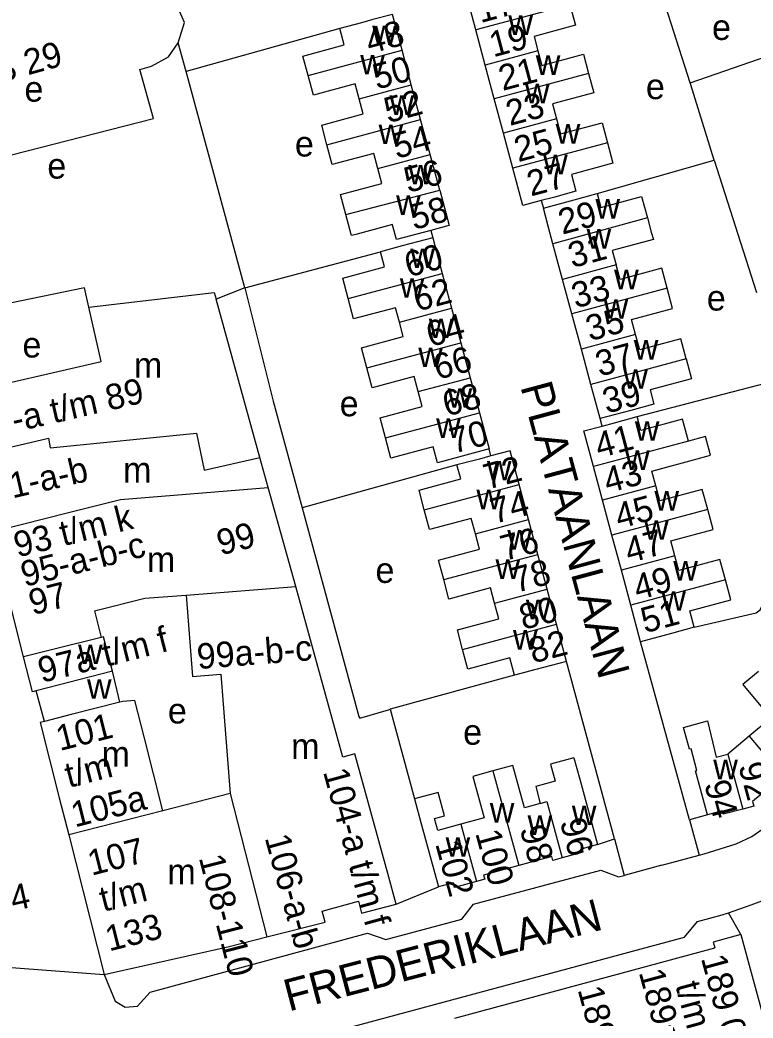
# Model space of a CAD drawing. Extents: x 159261 to 160849, y 382514 to 384534.
# Drawn here: x 159763.1 to 159878.4, y 383626.8 to 383783.7 of the extents above; entities that cross this region are included whole.
import ezdxf

# ---------------------------------------------------------------- set-up
doc = ezdxf.new("R2010")
doc.units = 0
for name, color, linetype in [('BLT_Basislijn', 7, 'Continuous'), ('BLT_Bebouwing', 7, 'Continuous'), ('BLT_Centroide', 7, 'Continuous'), ('BLT_Huisnummer', 7, 'Continuous'), ('BLT_Huisnummer_ tussenligend', 7, 'Continuous'), ('BLT_Huisnummer_reeks', 7, 'Continuous'), ('BLT_Onderdoorgang_en_onderverdeling', 7, 'Continuous'), ('BLT_Onderverdeling_panden', 7, 'Continuous'), ('BLT_Straatnaam', 7, 'Continuous'), ('BLT_Vlakafsluiter', 7, 'Continuous')]:
    doc.layers.add(name, color=color, linetype=linetype)

msp = doc.modelspace()

# ---------------------------------------------------------------- linework, layer by layer
at = {"layer": 'BLT_Basislijn'}
for p, q in [((159868.5, 383773.83), (159861.68, 383795.07)), ((159813.41, 383782.38), (159789.22, 383775.61)), ((159868.5, 383773.83), (159889.59, 383781.16)), ((159789.22, 383775.61), (159787.98, 383780.15)), ((159798.48, 383741.59), (159789.22, 383775.61)), ((159853.84, 383756.43), (159872.27, 383761.67)), ((159872.27, 383761.67), (159878.89, 383740.89)), ((159845.07, 383755.33), (159845.4, 383754.16)), ((159827.7, 383750.65), (159828.01, 383749.49)), ((159798.48, 383741.59), (159819.77, 383747.29)), ((159773.27, 383741.61), (159761.57, 383739.18)), ((159773.95, 383738.57), (159773.27, 383741.61)), ((159798.48, 383741.59), (159793.96, 383739.82)), ((159860.15, 383721.37), (159882.97, 383727.32)), ((159854.65, 383719.89), (159854.34, 383721.05)), ((159837.15, 383715.19), (159836.87, 383716.29)), ((159831.81, 383713.76), (159807.47, 383707.02)), ((159840.88, 383680.71), (159821.3, 383675.35)), ((159821.3, 383675.35), (159825.15, 383661.25)), ((159868.35, 383657.96), (159869.88, 383652.4)), ((159853.9, 383654.08), (159856.58, 383654.98)), ((159856.58, 383654.98), (159858.12, 383649.24)), ((159864, 383650.82), (159869.88, 383652.4)), ((159822.26, 383644.7), (159828.93, 383647.41)), ((159874.52, 383643.34), (159878.06, 383644.62)), ((159876.46, 383639.92), (159874.52, 383643.34))]:
    msp.add_line(p, q, dxfattribs=at)
for points in [[(159787.98, 383780.15), (159788.98, 383783.33), (159783.92, 383794.95)], [(159752.73, 383760.22), (159784.09, 383768.23), (159781.95, 383775.97), (159783.82, 383776.48), (159786.45, 383777.94), (159787.98, 383780.15)], [(159872.27, 383761.67), (159868.6, 383773.51), (159868.5, 383773.83)], [(159798.48, 383741.59), (159802.9, 383723.8), (159807.47, 383707.02)], [(159869.12, 383688.25), (159878.88, 383690.49), (159879.48, 383690.98), (159888.39, 383709.56), (159886.32, 383716.89), (159886.07, 383717.69)], [(159807.47, 383707.02), (159816.41, 383674.2), (159816.57, 383673.98), (159821.04, 383675.27), (159821.3, 383675.35)], [(159869.88, 383652.4), (159870.7, 383652.62), (159875.73, 383654.2), (159878.19, 383655.34), (159880.26, 383656.82), (159930.33, 383698.35)], [(159868.35, 383657.96), (159860.69, 383685.98)], [(159856.58, 383654.98), (159849.05, 383682.87)], [(159871.18, 383658.76), (159868.35, 383657.96)], [(159776.35, 383633.63), (159778.09, 383629.44), (159779.67, 383628.54), (159781.61, 383628.67), (159783.56, 383630.88), (159817.73, 383640.16), (159820.61, 383639.14), (159832.6, 383642.37), (159834.44, 383644.69), (159854.41, 383650.08), (159857.2, 383648.99), (159858.12, 383649.24)], [(159725.13, 383596.31), (159739.83, 383603.42), (159742.55, 383603.23), (159749.01, 383606.26), (159762.28, 383611.2), (159764.12, 383613.36), (159766.32, 383614.18), (159784.07, 383618.95), (159787.06, 383617.81), (159867.59, 383639.52), (159869.65, 383641.98), (159873.49, 383643.02), (159874.52, 383643.34)]]:
    msp.add_lwpolyline(points, dxfattribs=at)
at = {"layer": 'BLT_Bebouwing'}
for p, q in [((159834.78, 383782.16), (159833.28, 383787.73)), ((159836.25, 383776.65), (159834.78, 383782.16)), ((159824.64, 383773.54), (159823.18, 383778.96)), ((159837.68, 383771.32), (159836.25, 383776.65)), ((159826.11, 383768.07), (159824.64, 383773.54)), ((159839.12, 383765.94), (159837.68, 383771.32)), ((159827.59, 383762.59), (159826.11, 383768.07)), ((159840.6, 383760.41), (159839.12, 383765.94)), ((159829.1, 383756.99), (159827.59, 383762.59)), ((159828.01, 383749.49), (159829.5, 383743.89)), ((159848.42, 383742.94), (159846.91, 383748.55)), ((159829.5, 383743.89), (159830.97, 383738.4)), ((159849.89, 383737.51), (159848.42, 383742.94)), ((159800.85, 383714.93), (159793.96, 383739.82)), ((159775.88, 383730.03), (159773.95, 383738.57)), ((159830.97, 383738.4), (159832.41, 383732.98)), ((159851.39, 383731.96), (159849.89, 383737.51)), ((159832.41, 383732.98), (159833.88, 383727.48)), ((159852.88, 383726.43), (159851.39, 383731.96)), ((159833.88, 383727.48), (159835.35, 383721.96)), ((159854.34, 383721.05), (159852.88, 383726.43)), ((159835.35, 383721.96), (159836.87, 383716.29)), ((159802.16, 383710.2), (159800.85, 383714.93)), ((159854.7, 383708.21), (159853.27, 383713.51)), ((159806.46, 383694.65), (159802.16, 383710.2)), ((159843.07, 383705.18), (159841.59, 383710.7)), ((159856.18, 383702.71), (159854.7, 383708.21)), ((159844.54, 383699.7), (159843.07, 383705.18)), ((159857.66, 383697.22), (159856.18, 383702.71)), ((159846.01, 383694.23), (159844.54, 383699.7)), ((159859.14, 383691.72), (159857.66, 383697.22)), ((159809.94, 383682.06), (159806.46, 383694.65)), ((159847.48, 383688.72), (159846.01, 383694.23)), ((159774.84, 383690.84), (159782.76, 383692.81)), ((159782.76, 383692.81), (159789.23, 383693.28)), ((159860.69, 383685.98), (159859.14, 383691.72)), ((159774.84, 383690.84), (159775.89, 383686.64)), ((159778.84, 383676.45), (159777.64, 383681.32)), ((159794.69, 383680.85), (159796.17, 383662.09)), ((159766.96, 383673.44), (159765.65, 383678.24)), ((159766.96, 383673.44), (159766.3, 383673.28)), ((159766.3, 383673.28), (159767.83, 383667.26)), ((159784.1, 383665.19), (159782.62, 383671)), ((159877.77, 383671.12), (159874.38, 383668.31)), ((159767.83, 383667.26), (159769.3, 383661.44)), ((159785.57, 383659.37), (159784.1, 383665.19)), ((159769.3, 383661.44), (159770.78, 383655.62)), ((159770.78, 383655.62), (159776.35, 383633.63)), ((159831.46, 383626.81), (159872.35, 383637.87))]:
    msp.add_line(p, q, dxfattribs=at)
for points in [[(159849.57, 383786.12), (159850.43, 383782.89), (159843.94, 383781.15), (159844.55, 383778.87)], [(159818.6, 383783.78), (159816.83, 383783.3), (159813.41, 383782.38)], [(159823.18, 383778.96), (159821.66, 383784.6), (159818.6, 383783.78)], [(159808.44, 383774.99), (159807.61, 383778.06), (159814.1, 383779.81), (159813.41, 383782.38)], [(159844.55, 383778.87), (159845.16, 383776.59), (159851.69, 383778.33), (159852.5, 383775.3)], [(159816.46, 383771.33), (159815.82, 383773.68), (159809.27, 383771.92), (159808.44, 383774.99)], [(159852.5, 383775.3), (159853.32, 383772.26), (159846.83, 383770.52), (159847.46, 383768.17)], [(159811.38, 383764.1), (159810.55, 383767.21), (159817.09, 383768.97), (159816.46, 383771.33)], [(159847.46, 383768.17), (159848.08, 383765.82), (159854.64, 383767.58), (159855.49, 383764.39)], [(159819.39, 383760.38), (159818.75, 383762.75), (159812.22, 383760.99), (159811.38, 383764.1)], [(159855.49, 383764.39), (159856.34, 383761.21), (159849.81, 383759.46), (159850.53, 383756.79), (159847, 383755.84), (159845.07, 383755.33)], [(159814.35, 383753.13), (159813.53, 383756.27), (159820.02, 383758.02), (159819.39, 383760.38)], [(159845.07, 383755.33), (159842.17, 383754.55), (159840.6, 383760.41)], [(159829.1, 383756.99), (159830.59, 383751.43), (159830.18, 383751.32), (159827.7, 383750.65)], [(159845.4, 383754.16), (159850.23, 383755.46), (159853.84, 383756.43)], [(159853.84, 383756.43), (159854.43, 383754.24), (159860.83, 383755.98), (159861.76, 383752.6)], [(159846.91, 383748.55), (159846.16, 383751.32), (159845.4, 383754.16)], [(159827.7, 383750.65), (159822.32, 383749.19), (159821.74, 383751.32), (159821.67, 383751.55), (159815.9, 383750), (159815.22, 383749.82), (159815.17, 383750), (159814.35, 383753.13)], [(159861.76, 383752.6), (159862.37, 383750.37), (159862.72, 383749.24), (159856.23, 383747.49), (159856.85, 383745.21)], [(159828.01, 383749.49), (159823.18, 383748.2), (159819.77, 383747.29)], [(159814.7, 383739.94), (159813.85, 383743.16), (159820.41, 383744.91), (159819.77, 383747.29)], [(159864.86, 383741.54), (159864.01, 383744.71), (159857.46, 383742.94), (159856.85, 383745.21)], [(159859.9, 383734.26), (159859.26, 383736.64), (159865.71, 383738.38), (159864.86, 383741.54)], [(159773.95, 383738.57), (159793.67, 383740.87), (159793.96, 383739.82)], [(159822.78, 383736.21), (159822.17, 383738.49), (159815.56, 383736.72), (159814.7, 383739.94)], [(159817.64, 383729.03), (159816.8, 383732.18), (159823.38, 383733.94), (159822.78, 383736.21)], [(159867.84, 383730.47), (159866.99, 383733.61), (159860.55, 383731.87), (159859.9, 383734.26)], [(159867.84, 383730.47), (159868.69, 383727.33), (159862.19, 383725.57), (159862.76, 383723.32), (159859.16, 383722.35), (159854.34, 383721.05)], [(159753.55, 383724.92), (159775.88, 383730.03)], [(159825.71, 383725.3), (159825.09, 383727.65), (159818.48, 383725.88), (159817.64, 383729.03)], [(159820.6, 383718.02), (159819.75, 383721.2), (159826.34, 383722.96), (159825.71, 383725.3)], [(159854.65, 383719.89), (159856.59, 383720.41), (159860.15, 383721.37)], [(159868.21, 383717.53), (159867.29, 383720.94), (159860.74, 383719.17), (159860.15, 383721.37)], [(159853.27, 383713.51), (159851.76, 383719.11), (159854.65, 383719.89)], [(159836.87, 383716.29), (159832.04, 383715), (159828.75, 383714.12), (159828.08, 383716.62), (159821.44, 383714.85), (159820.6, 383718.02)], [(159863.1, 383710.47), (159862.47, 383712.81), (159869, 383714.57), (159871.68, 383715.29), (159870.88, 383718.25), (159868.21, 383717.53)], [(159837.15, 383715.19), (159835.35, 383714.7), (159831.81, 383713.76)], [(159841.59, 383710.7), (159840.18, 383716), (159837.15, 383715.19)], [(159826.68, 383706.7), (159825.85, 383709.8), (159832.4, 383711.56), (159831.81, 383713.76)], [(159871.23, 383706.77), (159870.38, 383709.92), (159863.73, 383708.13), (159863.1, 383710.47)], [(159866.08, 383699.49), (159865.45, 383701.82), (159872.08, 383703.61), (159871.23, 383706.77)], [(159834.71, 383702.94), (159834.07, 383705.36), (159827.51, 383703.6), (159826.68, 383706.7)], [(159763.65, 383683.59), (159759.43, 383700.31), (159761.45, 383700.79), (159760.99, 383702.63), (159759.42, 383703.42)], [(159829.73, 383695.74), (159828.91, 383698.79), (159835.36, 383700.51), (159834.71, 383702.94)], [(159874.01, 383695.73), (159873.16, 383698.89), (159866.71, 383697.15), (159866.08, 383699.49)], [(159837.73, 383692.01), (159837.08, 383694.44), (159830.55, 383692.69), (159829.73, 383695.74)], [(159869.12, 383688.25), (159868.42, 383690.83), (159874.87, 383692.57), (159874.01, 383695.73)], [(159789.23, 383693.28), (159790.24, 383680.5), (159794.69, 383680.85)], [(159832.7, 383684.76), (159831.88, 383687.85), (159838.38, 383689.59), (159837.73, 383692.01)], [(159849.05, 383682.87), (159847.48, 383688.72)], [(159869.12, 383688.25), (159865.52, 383687.28), (159860.69, 383685.98)], [(159775.89, 383686.64), (159768.5, 383684.8), (159763.65, 383683.59)], [(159777.64, 383681.32), (159776.25, 383686.73), (159775.89, 383686.64)], [(159765.65, 383678.24), (159765.07, 383678.09), (159763.65, 383683.59)], [(159840.88, 383680.71), (159840.15, 383683.44), (159833.53, 383681.67), (159832.7, 383684.76)], [(159822.26, 383644.7), (159820.93, 383649.52), (159815.75, 383668.35), (159813.88, 383667.83), (159809.94, 383682.06)], [(159849.05, 383682.87), (159844.21, 383681.59), (159840.88, 383680.71)], [(159879.24, 383681.31), (159876.75, 383679.24), (159881.15, 383673.94), (159877.77, 383671.12)], [(159778.84, 383676.45), (159771.15, 383674.51), (159766.96, 383673.44)], [(159782.62, 383671), (159781.17, 383676.74), (159779.31, 383676.57), (159778.84, 383676.45)], [(159867.45, 383672.51), (159871.21, 383673.53), (159872.54, 383667.8), (159874.38, 383668.31)], [(159871.18, 383658.76), (159869.31, 383665.67), (159869.53, 383665.73), (159868.61, 383669.13), (159868.38, 383669.07), (159867.45, 383672.51)], [(159850.2, 383667.73), (159846.53, 383666.73), (159847.26, 383664.04), (159844.19, 383663.2), (159844.91, 383660.54)], [(159850.2, 383667.73), (159851.12, 383664.34), (159853.9, 383654.08)], [(159844.91, 383660.54), (159842.43, 383659.86), (159840.61, 383666.52), (159837.46, 383665.66)], [(159837.46, 383665.66), (159834.32, 383664.8), (159836.11, 383658.27), (159832.45, 383657.27)], [(159883.04, 383664.77), (159878.3, 383660.84), (159878.49, 383660.14), (159876.76, 383659.67)], [(159796.17, 383662.09), (159785.57, 383659.37)], [(159832.45, 383657.27), (159828.79, 383656.27), (159828.27, 383658.17), (159829.87, 383658.6), (159828.87, 383662.27), (159825.15, 383661.25)], [(159825.15, 383661.25), (159826.15, 383657.57), (159827.61, 383652.23), (159828.93, 383647.41)], [(159876.76, 383659.67), (159873.68, 383658.84), (159873.53, 383659.4), (159871.18, 383658.76)], [(159853.9, 383654.08), (159851.48, 383653.42), (159851.63, 383652.86), (159848.38, 383651.97)], [(159848.38, 383651.97), (159846.89, 383651.56), (159846.71, 383652.21), (159841.53, 383650.79)], [(159841.53, 383650.79), (159836.01, 383649.29), (159836.19, 383648.62), (159834.91, 383648.27)], [(159834.91, 383648.27), (159831.44, 383647.32), (159831.25, 383648.04), (159828.93, 383647.41)], [(159801.95, 383639.55), (159811.11, 383641.87), (159810.64, 383643.6), (159816.36, 383645.18), (159816.83, 383643.32), (159822.26, 383644.7)], [(159776.35, 383633.63), (159796.01, 383638.05), (159801.95, 383639.55)], [(159876.46, 383639.92), (159872.11, 383638.75), (159872.35, 383637.87)], [(159876.46, 383639.92), (159880.62, 383624.55), (159878.71, 383624.02), (159879.98, 383619.32)]]:
    msp.add_lwpolyline(points, dxfattribs=at)
at = {"layer": 'BLT_Onderdoorgang_en_onderverdeling'}
msp.add_line((159777.64, 383681.32), (159765.65, 383678.24), dxfattribs=at)
at = {"layer": 'BLT_Onderverdeling_panden'}
for p, q in [((159849.57, 383786.12), (159834.78, 383782.16)), ((159808.44, 383774.99), (159823.18, 383778.96)), ((159844.55, 383778.87), (159836.25, 383776.65)), ((159852.5, 383775.3), (159837.68, 383771.32)), ((159816.46, 383771.33), (159824.64, 383773.54)), ((159811.38, 383764.1), (159826.11, 383768.07)), ((159847.46, 383768.17), (159839.12, 383765.94)), ((159855.49, 383764.39), (159840.6, 383760.41)), ((159819.39, 383760.38), (159827.59, 383762.59)), ((159814.35, 383753.13), (159829.1, 383756.99)), ((159861.76, 383752.6), (159846.91, 383748.55)), ((159856.85, 383745.21), (159848.42, 383742.94)), ((159814.7, 383739.94), (159829.5, 383743.89)), ((159864.86, 383741.54), (159849.89, 383737.51)), ((159822.78, 383736.21), (159830.97, 383738.4)), ((159859.9, 383734.26), (159851.39, 383731.96)), ((159817.64, 383729.03), (159832.41, 383732.98)), ((159867.84, 383730.47), (159852.88, 383726.43)), ((159825.71, 383725.3), (159833.88, 383727.48)), ((159820.6, 383718.02), (159835.35, 383721.96)), ((159767.88, 383716.44), (159790.86, 383718.78)), ((159868.21, 383717.53), (159853.27, 383713.51)), ((159778.9, 383708.36), (159802.16, 383710.2)), ((159826.68, 383706.7), (159841.59, 383710.7)), ((159863.1, 383710.47), (159854.7, 383708.21)), ((159770.98, 383706.35), (159778.9, 383708.36)), ((159871.23, 383706.77), (159856.18, 383702.71)), ((159759.42, 383703.42), (159770.98, 383706.35)), ((159834.71, 383702.94), (159843.07, 383705.18)), ((159829.73, 383695.74), (159844.54, 383699.7)), ((159866.08, 383699.49), (159857.66, 383697.22)), ((159789.23, 383693.28), (159806.46, 383694.65)), ((159837.73, 383692.01), (159846.01, 383694.23)), ((159874.01, 383695.73), (159859.14, 383691.72)), ((159832.7, 383684.76), (159847.48, 383688.72)), ((159877.77, 383671.12), (159883.04, 383664.77)), ((159874.38, 383668.31), (159876.76, 383659.67)), ((159837.46, 383665.66), (159841.53, 383650.79)), ((159796.17, 383662.09), (159801.95, 383639.55)), ((159785.57, 383659.37), (159770.78, 383655.62)), ((159832.45, 383657.27), (159834.91, 383648.27))]:
    msp.add_line(p, q, dxfattribs=at)
for points in [[(159755.76, 383715.2), (159767.58, 383717.96), (159767.88, 383716.44)], [(159790.86, 383718.78), (159792.07, 383712.94), (159800.85, 383714.93)], [(159844.91, 383660.54), (159845.96, 383660.83), (159848.38, 383651.97)]]:
    msp.add_lwpolyline(points, dxfattribs=at)
at = {"layer": 'BLT_Vlakafsluiter'}
for p, q in [((159864, 383650.82), (159858.12, 383649.24)), ((159878.06, 383644.62), (159881.6, 383645.9)), ((159761.06, 383634.82), (159776.35, 383633.63))]:
    msp.add_line(p, q, dxfattribs=at)

# ---------------------------------------------------------------- texts
at = {"layer": 'BLT_Centroide'}
for s, p in [('w', (159839.9, 383781.38)), ('e', (159871.92, 383780.59)), ('w', (159818.49, 383779.78)), ('w', (159816.61, 383775.16)), ('w', (159844.21, 383775.09)), ('e', (159861.52, 383771.28)), ('e', (159763.82, 383770.89)), ('w', (159842.52, 383770.62)), ('w', (159821.21, 383768.81)), ('w', (159819.49, 383764.22)), ('w', (159847.34, 383764.28)), ('e', (159806.34, 383762.26)), ('e', (159767.42, 383758.79)), ('w', (159845.36, 383759.47)), ('w', (159824.16, 383757.88)), ('w', (159822.25, 383753.09)), ('w', (159853.59, 383752.5)), ('w', (159852.2, 383747.78)), ('w', (159824.48, 383744.72)), ('w', (159856.52, 383741.38)), ('w', (159822.83, 383740.06)), ('w', (159854.88, 383736.75)), ('e', (159871.1, 383738.04)), ('w', (159827.38, 383733.72)), ('e', (159763.51, 383730.66)), ('w', (159825.74, 383729.16)), ('w', (159859.61, 383730.34)), ('m', (159781.03, 383727.47)), ('w', (159857.97, 383725.75)), ('w', (159830.35, 383722.75)), ('e', (159813.38, 383721.42)), ('w', (159828.54, 383718.03)), ('w', (159859.78, 383717.56)), ('w', (159858.25, 383712.97)), ('m', (159779.33, 383711)), ('w', (159836.52, 383711.34)), ('w', (159834.88, 383706.81)), ('w', (159862.86, 383706.59)), ('w', (159861.23, 383702)), ('w', (159839.74, 383700.47)), ('m', (159783.07, 383696.91)), ('w', (159837.88, 383695.84)), ('e', (159819.01, 383695.22)), ('w', (159865.82, 383695.59)), ('w', (159863.94, 383690.84)), ('w', (159842.65, 383689.5)), ('w', (159840.63, 383684.72)), ('w', (159772.25, 383682.45)), ('w', (159773.66, 383677)), ('e', (159786.37, 383673.12)), ('e', (159832.79, 383669.78)), ('m', (159805.75, 383667.55)), ('m', (159775.94, 383666.33)), ('w', (159872.11, 383664.34)), ('w', (159836.98, 383657.55)), ('w', (159849.88, 383657.14)), ('w', (159842.92, 383655.59)), ('w', (159830.03, 383652.16)), ('m', (159786.29, 383647.84))]:
    msp.add_text(s, height=4, dxfattribs=at).set_placement(p)
at = {"layer": 'BLT_Huisnummer'}
for s, rotation, p in [('17', 14.9924, (159835.5, 383783.23)), ('48', 15.0891, (159818.09, 383778.37)), ('21', 14.9768, (159838.99, 383772.56)), ('52', 15.077, (159820.98, 383767.49)), ('25', 14.9903, (159841.43, 383761.36)), ('56', 15.1459, (159824.12, 383756.52)), ('29', 15.0841, (159848.37, 383749.96)), ('60', 14.941, (159824.19, 383743.24)), ('33', 15.0854, (159850.46, 383738.37)), ('64', 14.9388, (159827.61, 383732.29)), ('37', 15.0923, (159854.22, 383727.64)), ('68', 14.9542, (159830.17, 383721.36)), ('41', 15.0881, (159854.14, 383714.8)), ('72', 14.9899, (159836.6, 383709.87)), ('51', 15.0839, (159861.35, 383687.29)), ('82', 14.801, (159843.76, 383682.54)), ('94', 285.1533, (159870.66, 383663.64)), ('96', 285.2893, (159847.96, 383657.68)), ('102', 285.2814, (159828.38, 383654.21))]:
    msp.add_text(s, height=4, rotation=rotation, dxfattribs=at).set_placement(p)
at = {"layer": 'BLT_Huisnummer_ tussenligend'}
for s, rotation, p in [('19', 14.9924, (159837.53, 383777.85)), ('50', 15.0891, (159819.2, 383772.76)), ('23', 14.9768, (159840.12, 383767.06)), ('54', 15.077, (159822.31, 383761.88)), ('27', 14.9903, (159843.43, 383755.97)), ('58', 15.1459, (159825.03, 383750.69)), ('31', 15.0841, (159849.93, 383744.7)), ('62', 14.941, (159825.55, 383737.86)), ('35', 15.0854, (159852.7, 383733.21)), ('66', 14.9388, (159828.74, 383727.13)), ('39', 15.0923, (159855.34, 383721.81)), ('70', 14.9542, (159831.28, 383715.53)), ('43', 15.0881, (159855.5, 383709.3)), ('74', 14.9899, (159837.7, 383704.48)), ('45', 15.0881, (159857.29, 383703.69)), ('76', 14.9899, (159839.27, 383698.65)), ('47', 15.0881, (159858.84, 383698.31)), ('78', 14.9999, (159841.12, 383693.65)), ('49', 15.0881, (159860.2, 383692.48)), ('80', 14.9999, (159842.24, 383687.81)), ('92', 285.1533, (159876.03, 383666.47)), ('98', 285.2893, (159841.66, 383656.57)), ('100', 285.2893, (159834.67, 383655.89))]:
    msp.add_text(s, height=4, rotation=rotation, dxfattribs=at).set_placement(p)
at = {"layer": 'BLT_Huisnummer_reeks'}
for s, rotation, p in [('73 01t/m73 29', 15.6501, (159737.15, 383767.4)), ('87-a t/m 89', 12.8885, (159756.49, 383717.58)), ('91-a-b', 12.8922, (159759.03, 383707.83)), ('93 t/m k', 13.9705, (159762.71, 383699.2)), ('99', 14.2179, (159794.64, 383699.53)), ('95-a-b-c', 14.2179, (159763.83, 383694.57)), ('97', 14.2179, (159765.09, 383690.13)), ('97a t/m f', 14.1642, (159766.53, 383679.48)), ('99a-b-c', 4.517, (159791.08, 383681.66)), ('101', 14.222, (159769.37, 383668.78)), ('t/m', 14.3802, (159770.79, 383662.98)), ('104-a t/m f', 285.3869, (159810.74, 383665.54)), ('105a', 14.222, (159771.74, 383656.77)), ('107', 14.222, (159774.35, 383649.17)), ('106-a-b', 285.3869, (159801.57, 383655.15)), ('108-110', 284.3808, (159791.22, 383652.02)), ('172-174', 12.818, (159745.84, 383639.9)), ('t/m', 14.3802, (159776.22, 383643.48)), ('133', 14.222, (159777.13, 383637.27)), ('189 01', 285.1876, (159870.15, 383636.22)), ('189a-b', 285.246, (159860.38, 383634)), ('189 83', 285.1876, (159850.77, 383631.28)), ('t/m', 285.1876, (159866.12, 383631.98))]:
    msp.add_text(s, height=4, rotation=rotation, dxfattribs=at).set_placement(p)
at = {"layer": 'BLT_Straatnaam'}
for s, rotation, p in [('PLATAANLAAN', 285.0898, (159841.76, 383726.11)), ('FREDERIKLAAN', 14.6317, (159805.37, 383627.82))]:
    msp.add_text(s, height=5, rotation=rotation, dxfattribs=at).set_placement(p)

doc.saveas('drawing.dxf')
